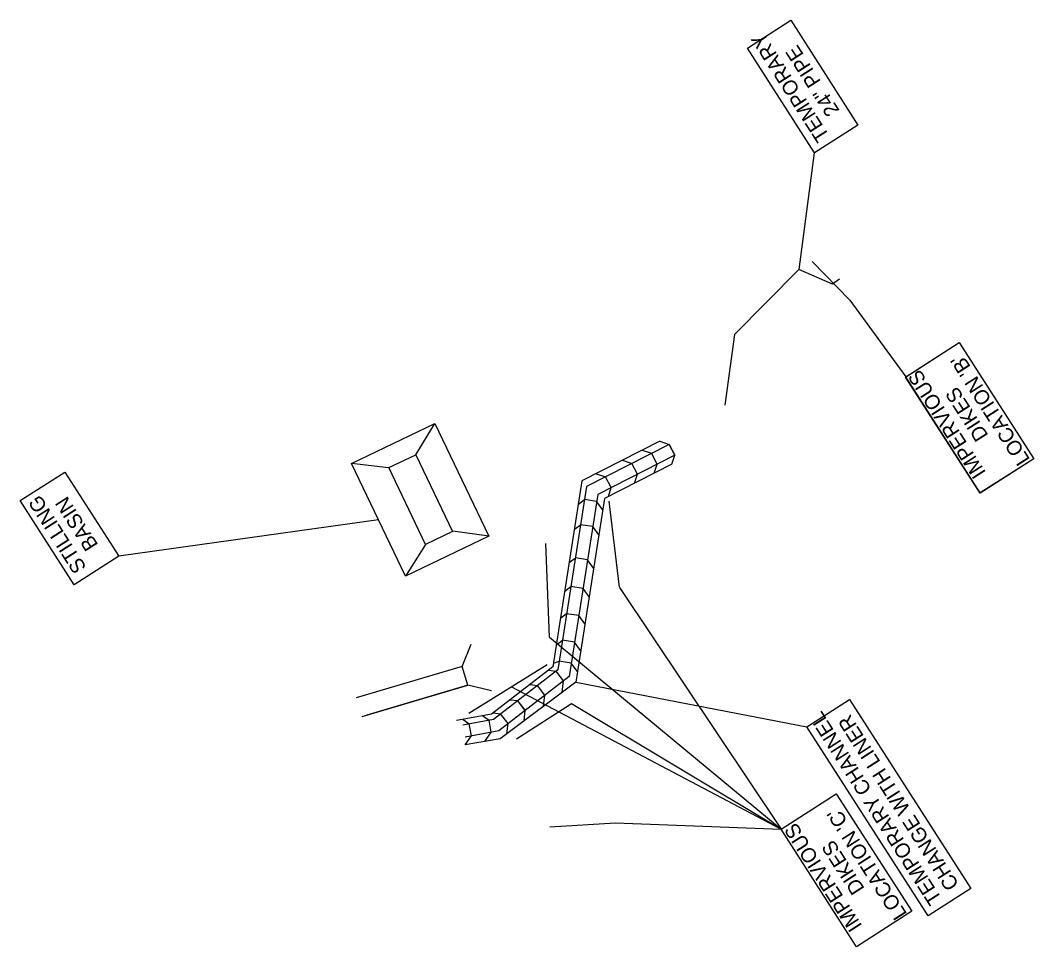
# Model space of a CAD drawing. Extents: x 476586 to 481096, y 489307 to 500930.
# Drawn here: x 477668.1 to 478081, y 499256.7 to 499634.1 of the extents above; entities that cross this region are included whole.
import ezdxf

# ---------------------------------------------------------------- set-up
doc = ezdxf.new("R2010")
doc.units = 0
for name, color, linetype in [('Impervious Dike CG', 7, 'Continuous'), ('Impervious Dike Note CG CELL', 7, 'Continuous'), ('Prop Grid Mask', 7, 'Continuous'), ('Prop Roadway Culvert', 7, 'Continuous'), ('Stilling Basin CG CELL', 7, 'Continuous'), ('Stilling Basin Storage Note CG CELL', 7, 'Continuous'), ('Temporary Channel Change Inside CG', 7, 'Continuous'), ('Temporary Channel Change with Liner Note CG CELL', 7, 'Continuous'), ('Temporary Pipe CG', 7, 'Continuous')]:
    doc.layers.add(name, color=color, linetype=linetype)

msp = doc.modelspace()

# ---------------------------------------------------------------- linework, layer by layer
at = {"layer": 'Impervious Dike CG'}
for p, q in [((478006.08, 499520.07), (477990.74, 499535.87)), ((477912.24, 499403.18), (477908.01, 499438.26)), ((477883.75, 499382.85), (477882.16, 499420.91)), ((477870.23, 499341.38), (477892.73, 499355.81)), ((477883.86, 499305.48), (477910.55, 499307.12))]:
    msp.add_line(p, q, dxfattribs=at)
msp.add_lwpolyline([(477882.76, 499371.51), (477850.83, 499351.71)], dxfattribs=at)
at = {"layer": 'Impervious Dike Note CG CELL'}
for points in [[(477991.73, 499580.15), (477964.35, 499622.82), (477981.99, 499634.14), (478009.36, 499591.46)], [(478059.11, 499441.47), (478028.75, 499488.78), (478050.65, 499502.83), (478081, 499455.51)], [(478008.77, 499256.69), (477978.06, 499304.59), (478000.57, 499319.02), (478031.28, 499271.13)]]:
    msp.add_lwpolyline(points, close=True, dxfattribs=at)
at = {"layer": 'Prop Grid Mask'}
for points in [[(477991.73, 499580.15), (477964.35, 499622.82), (477981.98, 499634.14), (478009.36, 499591.46)], [(478059.24, 499441.55), (478028.88, 499488.86), (478050.65, 499502.83), (478081, 499455.51)], [(477690.08, 499404.19), (477668.1, 499438.45), (477686.24, 499450.08), (477708.22, 499415.83)], [(478037.97, 499269.26), (477988.59, 499346.24), (478005.97, 499357.39), (478055.35, 499280.42)], [(478008.78, 499256.7), (477978.06, 499304.59), (478000.56, 499319.02), (478031.28, 499271.13)]]:
    msp.add_lwpolyline(points, close=True, dxfattribs=at)
at = {"layer": 'Prop Roadway Culvert'}
for p, q in [((477848.1, 499370.9), (477851.87, 499379.94)), ((477848.11, 499370.91), (477804.98, 499358.09)), ((477850.49, 499363.26), (477848.1, 499370.9)), ((477807.35, 499350.45), (477850.49, 499363.26)), ((477860.12, 499360.99), (477850.49, 499363.26))]:
    msp.add_line(p, q, dxfattribs=at)
at = {"layer": 'Stilling Basin CG CELL'}
for p, q in [((477803.01, 499453.51), (477836.96, 499469.88)), ((477829.25, 499457.15), (477836.96, 499469.88)), ((477836.97, 499469.92), (477848, 499446.97)), ((477818.28, 499451.87), (477829.25, 499457.15)), ((477829.25, 499457.15), (477844.24, 499425.91)), ((477814.03, 499430.57), (477803.01, 499453.51)), ((477818.18, 499451.84), (477803.01, 499453.51)), ((477833.23, 499420.6), (477818.28, 499451.87)), ((477848, 499446.97), (477859.06, 499424)), ((477825.07, 499407.65), (477814.03, 499430.57)), ((477859.06, 499424), (477825.07, 499407.65)), ((477844.24, 499425.91), (477833.23, 499420.6)), ((477859.06, 499424), (477844.27, 499425.95)), ((477833.23, 499420.6), (477825.07, 499407.65))]:
    msp.add_line(p, q, dxfattribs=at)
at = {"layer": 'Stilling Basin Storage Note CG CELL'}
for p, q in [((477985.41, 499532.59), (477991.73, 499580.15)), ((478006.08, 499520.07), (478028.88, 499488.86)), ((477814.03, 499430.57), (477708.22, 499415.83)), ((477912.26, 499403.03), (477978.06, 499304.59)), ((477883.75, 499382.85), (477978.06, 499304.59)), ((477850.49, 499363.26), (477809.27, 499351.02)), ((477868.28, 499362.53), (477978.06, 499304.59)), ((477894.39, 499364.5), (477988.59, 499346.24)), ((477892.73, 499355.81), (477978.06, 499304.59)), ((477910.55, 499307.12), (477978.06, 499304.59))]:
    msp.add_line(p, q, dxfattribs=at)
msp.add_lwpolyline([(477690.08, 499404.19), (477668.1, 499438.45), (477686.24, 499450.08), (477708.22, 499415.83)], close=True, dxfattribs=at)
at = {"layer": 'Temporary Channel Change Inside CG'}
for p, q in [((477928.64, 499462.61), (477932.45, 499461.37)), ((477934.72, 499456.92), (477932.45, 499461.37)), ((477932.45, 499461.37), (477934.72, 499456.92)), ((477921.48, 499458.96), (477925.3, 499457.72)), ((477927.57, 499453.27), (477925.3, 499457.72)), ((477933.56, 499453.34), (477934.72, 499456.92)), ((477913.45, 499454.86), (477917.26, 499453.62)), ((477919.54, 499449.17), (477917.26, 499453.62)), ((477926.41, 499449.69), (477927.57, 499453.27)), ((477902.78, 499449.42), (477906.59, 499448.18)), ((477918.37, 499445.59), (477919.54, 499449.17)), ((477908.87, 499443.73), (477906.59, 499448.18)), ((477907.71, 499440.15), (477908.87, 499443.73)), ((477895.47, 499437.06), (477897.97, 499438.88)), ((477902.91, 499438.11), (477897.97, 499438.88)), ((477905.39, 499434.7), (477902.91, 499438.11)), ((477893.87, 499426.82), (477896.37, 499428.64)), ((477901.31, 499427.87), (477896.37, 499428.64)), ((477903.79, 499424.46), (477901.31, 499427.87)), ((477891.75, 499413.29), (477894.25, 499415.11)), ((477899.19, 499414.34), (477894.25, 499415.11)), ((477901.68, 499410.93), (477899.19, 499414.34)), ((477889.93, 499401.61), (477892.43, 499403.43)), ((477897.37, 499402.66), (477892.43, 499403.43)), ((477899.85, 499399.25), (477897.37, 499402.66)), ((477888.2, 499390.56), (477890.7, 499392.39)), ((477895.64, 499391.59), (477890.7, 499392.36)), ((477898.1, 499388.19), (477895.61, 499391.59)), ((477886.51, 499379.75), (477889.01, 499381.57)), ((477893.95, 499380.78), (477889.01, 499381.55)), ((477896.41, 499377.38), (477893.92, 499380.78)), ((477885.32, 499372.16), (477887.67, 499373.04)), ((477892.61, 499372.24), (477887.67, 499373.01)), ((477895.07, 499368.84), (477892.59, 499372.24)), ((477883.34, 499369.36), (477886.41, 499368.98)), ((477889.47, 499365.02), (477886.39, 499368.96)), ((477875.72, 499363.48), (477878.8, 499363.1)), ((477881.85, 499359.14), (477878.78, 499363.08)), ((477888.87, 499360.35), (477889.45, 499365.04)), ((477881.27, 499354.64), (477881.83, 499359.16)), ((477867.76, 499357.34), (477870.83, 499356.95)), ((477873.87, 499352.98), (477870.81, 499356.94)), ((477873.89, 499353), (477870.81, 499356.94)), ((477848.51, 499349.28), (477851.05, 499347.51)), ((477856.6, 499350.77), (477859.14, 499349)), ((477860.77, 499351.94), (477863.84, 499351.56)), ((477866.89, 499347.6), (477863.82, 499351.54)), ((477873.34, 499348.68), (477873.87, 499353.01)), ((477851.91, 499342.59), (477851.03, 499347.51)), ((477851.94, 499342.58), (477851.03, 499347.5)), ((477859.99, 499344.08), (477859.11, 499349)), ((477866.36, 499343.43), (477866.88, 499347.62)), ((477849.31, 499338.89), (477851.91, 499342.61)), ((477857.34, 499340.3), (477859.99, 499344.1))]:
    msp.add_line(p, q, dxfattribs=at)
for points in [[(477928.64, 499462.61), (477896.94, 499446.44)], [(477932.45, 499461.37), (477898.8, 499444.21)], [(477934.73, 499456.92), (477903.35, 499440.91)], [(477933.56, 499453.34), (477906.09, 499439.32)], [(477896.94, 499446.44), (477885.1, 499370.71)], [(477898.8, 499444.21), (477887.13, 499369.53)], [(477903.35, 499440.91), (477891.76, 499366.79), (477863.05, 499344.63), (477849.33, 499342.1)], [(477906.09, 499439.32), (477895.07, 499368.84), (477894.39, 499364.5), (477866.36, 499343.43), (477863.59, 499341.41), (477849.31, 499338.89)], [(477885.1, 499370.71), (477860.09, 499351.41)], [(477887.13, 499369.53), (477860.96, 499349.33)], [(477860.09, 499351.41), (477845.88, 499348.8)], [(477860.96, 499349.33), (477848.42, 499347.02)]]:
    msp.add_lwpolyline(points, dxfattribs=at)
at = {"layer": 'Temporary Channel Change with Liner Note CG CELL'}
msp.add_lwpolyline([(478037.97, 499269.26), (477988.59, 499346.24), (478005.97, 499357.39), (478055.35, 499280.42)], close=True, dxfattribs=at)
at = {"layer": 'Temporary Pipe CG'}
for p, q in [((477985.35, 499532.62), (477959.06, 499506.1)), ((477959.06, 499506.1), (477955.1, 499477.29))]:
    msp.add_line(p, q, dxfattribs=at)
msp.add_lwpolyline([(478001.86, 499528.61), (477998.97, 499526.6), (477985.35, 499532.62)], dxfattribs=at)

# ---------------------------------------------------------------- texts
at = {"layer": 'Impervious Dike Note CG CELL'}
for s, p in [('TEMPORARY', (477998.02, 499586.98)), ('24" PIPE', (478002.05, 499597.37)), ("LOCATION 'B'", (478079.7, 499455.19)), ('IMPERVIOUS', (478061.72, 499449.87)), ('DIKES', (478062.71, 499465)), ("LOCATION 'C'", (478029.58, 499270.07)), ('IMPERVIOUS', (478011.31, 499265.22)), ('DIKES', (478012.29, 499280.35))]:
    msp.add_text(s, height=6, rotation=122.6818, dxfattribs=at).set_placement(p)
at = {"layer": 'Stilling Basin Storage Note CG CELL'}
for s, p in [('STILLING', (477695.26, 499411.22)), ('BASIN', (477700.05, 499420.4))]:
    msp.add_text(s, height=6, rotation=122.6818, dxfattribs=at).set_placement(p)
at = {"layer": 'Temporary Channel Change with Liner Note CG CELL'}
for s, p in [('TEMPORARY CHANNEL', (478043.82, 499276.17)), ('CHANGE WITH LINER', (478050.76, 499282.03))]:
    msp.add_text(s, height=6, rotation=122.6818, dxfattribs=at).set_placement(p)

doc.saveas('drawing.dxf')
